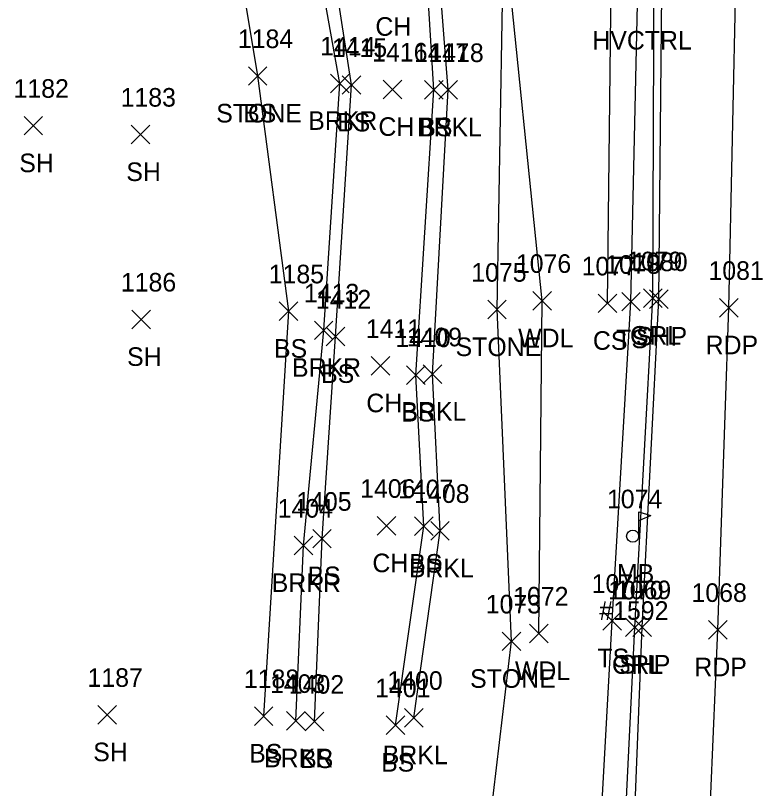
# Model space of a CAD drawing. Extents: x 1618262 to 1622220, y 273782 to 283685.
# Drawn here: x 1621974.4 to 1622054.7, y 282582.4 to 282665.6 of the extents above; entities that cross this region are included whole.
import ezdxf

# ---------------------------------------------------------------- set-up
doc = ezdxf.new("R2010")
doc.units = 0
for name, color, linetype in [('C_A', 7, 'Continuous'), ('L_A', 7, 'Continuous'), ('L_C', 7, 'Continuous'), ('L_I', 7, 'Continuous'), ('L_TIC', 7, 'Continuous'), ('LASF', 7, 'Continuous'), ('LAWA', 7, 'Continuous'), ('LAWE', 7, 'Continuous'), ('LELB', 7, 'Continuous'), ('LMB', 7, 'Continuous'), ('P_A', 7, 'Continuous'), ('P_I', 7, 'Continuous'), ('P_TIC', 7, 'Continuous'), ('PET', 7, 'Continuous'), ('PSP', 7, 'Continuous'), ('R_A', 7, 'Continuous'), ('R_I', 7, 'Continuous'), ('R_TIC', 7, 'Continuous'), ('RGR', 7, 'Continuous')]:
    doc.layers.add(name, color=color, linetype=linetype)

msp = doc.modelspace()

# ---------------------------------------------------------------- linework, layer by layer
at = {"layer": 'L_TIC'}
for points in [[(1621999.409, 282658.069), (1622001.409, 282660.069)], [(1622001.409, 282658.069), (1621999.409, 282660.069)], [(1621999.409, 282658.069), (1622001.409, 282660.069)], [(1622001.409, 282658.069), (1621999.409, 282660.069)], [(1622008.259, 282657.274), (1622010.259, 282659.274)], [(1622010.259, 282657.274), (1622008.259, 282659.274)], [(1622009.519, 282657.102), (1622011.519, 282659.102)], [(1622011.519, 282657.102), (1622009.519, 282659.102)], [(1622013.915, 282656.626), (1622015.915, 282658.626)], [(1622015.915, 282656.626), (1622013.915, 282658.626)], [(1622018.353, 282656.587), (1622020.353, 282658.587)], [(1622020.353, 282656.587), (1622018.353, 282658.587)], [(1622019.908, 282656.569), (1622021.908, 282658.569)], [(1622021.908, 282656.569), (1622019.908, 282658.569)], [(1621975.275, 282652.722), (1621977.275, 282654.722)], [(1621977.275, 282652.722), (1621975.275, 282654.722)], [(1621986.792, 282651.771), (1621988.792, 282653.771)], [(1621988.792, 282651.771), (1621986.792, 282653.771)], [(1622030.019, 282633.894), (1622032.019, 282635.894)], [(1622032.019, 282633.894), (1622030.019, 282635.894)], [(1622037.036, 282633.62), (1622039.036, 282635.62)], [(1622039.036, 282633.62), (1622037.036, 282635.62)], [(1622039.575, 282633.794), (1622041.575, 282635.794)], [(1622041.575, 282633.794), (1622039.575, 282635.794)], [(1622002.727, 282632.768), (1622004.727, 282634.768)], [(1622004.727, 282632.768), (1622002.727, 282634.768)], [(1622025.162, 282632.945), (1622027.162, 282634.945)], [(1622027.162, 282632.945), (1622025.162, 282634.945)], [(1621986.876, 282631.889), (1621988.876, 282633.889)], [(1621988.876, 282631.889), (1621986.876, 282633.889)], [(1622006.513, 282630.716), (1622008.513, 282632.716)], [(1622008.513, 282630.716), (1622006.513, 282632.716)], [(1622007.796, 282630.06), (1622009.796, 282632.06)], [(1622009.796, 282630.06), (1622007.796, 282632.06)], [(1622012.613, 282626.902), (1622014.613, 282628.902)], [(1622014.613, 282626.902), (1622012.613, 282628.902)], [(1622016.432, 282625.905), (1622018.432, 282627.905)], [(1622018.432, 282625.905), (1622016.432, 282627.905)], [(1622018.223, 282625.996), (1622020.223, 282627.996)], [(1622020.223, 282625.996), (1622018.223, 282627.996)], [(1622013.265, 282609.701), (1622015.265, 282611.701)], [(1622015.265, 282609.701), (1622013.265, 282611.701)], [(1622017.278, 282609.651), (1622019.278, 282611.651)], [(1622019.278, 282609.651), (1622017.278, 282611.651)], [(1622019.028, 282609.154), (1622021.028, 282611.154)], [(1622021.028, 282609.154), (1622019.028, 282611.154)], [(1622004.333, 282607.569), (1622006.333, 282609.569)], [(1622006.333, 282607.569), (1622004.333, 282609.569)], [(1622006.334, 282608.31), (1622008.334, 282610.31)], [(1622008.334, 282608.31), (1622006.334, 282610.31)], [(1622037.549, 282599.481), (1622039.549, 282601.481)], [(1622039.549, 282599.481), (1622037.549, 282601.481)], [(1622029.671, 282598.119), (1622031.671, 282600.119)], [(1622031.671, 282598.119), (1622029.671, 282600.119)], [(1622026.724, 282597.268), (1622028.724, 282599.268)], [(1622028.724, 282597.268), (1622026.724, 282599.268)], [(1621983.232, 282589.373), (1621985.232, 282591.373)], [(1621985.232, 282589.373), (1621983.232, 282591.373)], [(1622000.056, 282589.233), (1622002.056, 282591.233)], [(1622002.056, 282589.233), (1622000.056, 282591.233)], [(1622003.508, 282588.719), (1622005.508, 282590.719)], [(1622005.508, 282588.719), (1622003.508, 282590.719)], [(1622005.532, 282588.636), (1622007.532, 282590.636)], [(1622007.532, 282588.636), (1622005.532, 282590.636)], [(1622016.226, 282589.052), (1622018.226, 282591.052)], [(1622018.226, 282589.052), (1622016.226, 282591.052)], [(1622014.253, 282588.258), (1622016.253, 282590.258)], [(1622016.253, 282588.258), (1622014.253, 282590.258)]]:
    msp.add_lwpolyline(points, dxfattribs=at)
at = {"layer": 'LASF'}
msp.add_lwpolyline([(1622017.991, 282482.049), (1622021.545, 282521.435), (1622023.199, 282560.154), (1622027.724, 282598.268), (1622026.162, 282633.945), (1622026.882, 282675.285), (1622029.94, 282679.448), (1622032.966, 282688.79), (1622033.094, 282693.395), (1622031.462, 282708.807), (1622023.774, 282712.352), (1622021.815, 282710.839), (1622017.17, 282709.218), (1622015.049, 282702.038), (1622004.918, 282698.84), (1621996.66, 282681.559), (1622000.409, 282659.069)], dxfattribs=at)
at = {"layer": 'LAWA'}
msp.add_lwpolyline([(1622030.671, 282599.119), (1622031.019, 282634.894), (1622026.882, 282675.285), (1622025.785, 282678.835)], dxfattribs=at)
at = {"layer": 'LAWE'}
for points in [[(1622004.508, 282589.719), (1622005.333, 282608.569), (1622007.513, 282631.716), (1622009.259, 282658.274), (1622005.37, 282679.941), (1622009.389, 282692.601), (1622016.472, 282697.474), (1622023.015, 282700.983)], [(1622017.226, 282590.052), (1622020.028, 282610.154), (1622019.223, 282626.996), (1622020.908, 282657.569), (1622019.553, 282675.131), (1622022.862, 282678.636)]]:
    msp.add_lwpolyline(points, dxfattribs=at)
at = {"layer": 'LELB'}
for points in [[(1622031.53, 282480.209), (1622034.92, 282519.516), (1622036.308, 282559.668), (1622038.549, 282600.481), (1622040.575, 282634.794), (1622041.384, 282671.626), (1622041.057, 282708.261), (1622040.536, 282746.865), (1622039.334, 282766.475), (1622038.366, 282807.145), (1622036.997, 282847.689), (1622035.465, 282881.364), (1622030.123, 282906.905), (1622032.201, 282930.97)], [(1622038.036, 282634.62), (1622038.492, 282672.044), (1622038.146, 282708.503), (1622036.634, 282747.032), (1622027.782, 282767.08)], [(1622015.253, 282589.258), (1622018.278, 282610.651), (1622017.432, 282626.905), (1622019.353, 282657.587), (1622018.302, 282675.18), (1622022.753, 282682.471), (1622023.259, 282685.553), (1622022.974, 282687.958), (1622023.158, 282690.363), (1622022.911, 282694.814), (1622022.926, 282698.21), (1622023.015, 282700.983), (1622022.752, 282703.296)], [(1622006.532, 282589.636), (1622007.334, 282609.31), (1622008.796, 282631.06), (1622010.519, 282658.102), (1622007.168, 282679.656), (1622011.291, 282692.087), (1622017.342, 282696.584), (1622022.926, 282698.21)], [(1622000.409, 282659.069), (1622003.727, 282633.768), (1622001.056, 282590.233)]]:
    msp.add_lwpolyline(points, dxfattribs=at)
at = {"layer": 'LMB'}
for p, q in [((1622041.41, 282612.177), (1622042.704, 282611.795)), ((1622041.416, 282609.585), (1622041.415, 282612.179)), ((1622041.415, 282611.278), (1622042.697, 282611.786)), ((1622040.76, 282609.576), (1622040.76, 282609.576))]:
    msp.add_line(p, q, dxfattribs=at)
msp.add_circle((1622040.76, 282609.576), 0.656, dxfattribs=at)
at = {"layer": 'P_TIC'}
for points in [[(1622042.576, 282634.077), (1622044.576, 282636.077)], [(1622044.576, 282634.077), (1622042.576, 282636.077)], [(1622050.114, 282633.143), (1622052.114, 282635.143)], [(1622052.114, 282633.143), (1622050.114, 282635.143)], [(1622040.775, 282598.797), (1622042.775, 282600.797)], [(1622042.775, 282598.797), (1622040.775, 282600.797)], [(1622048.907, 282598.505), (1622050.907, 282600.505)], [(1622050.907, 282598.505), (1622048.907, 282600.505)]]:
    msp.add_lwpolyline(points, dxfattribs=at)
at = {"layer": 'PET'}
msp.add_lwpolyline([(1622031.404, 282363.078), (1622036.529, 282409.612), (1622039.656, 282443.455), (1622042.912, 282478.81), (1622045.922, 282518.248), (1622048.156, 282558.34), (1622049.907, 282599.505), (1622051.114, 282634.143), (1622051.904, 282670.586), (1622052.331, 282709.809), (1622052.148, 282746.848), (1622051.427, 282768.15), (1622050.471, 282807.305), (1622048.588, 282847.854), (1622046.49, 282883.042), (1622043.219, 282932.276)], dxfattribs=at)
at = {"layer": 'PSP'}
msp.add_lwpolyline([(1622024.53, 282364.695), (1622029.224, 282410.341), (1622032.133, 282444.404), (1622034.721, 282480.169), (1622038.065, 282518.937), (1622040.189, 282559.981), (1622041.775, 282599.797), (1622043.576, 282635.077), (1622043.931, 282671.705), (1622044.179, 282709.624), (1622044.427, 282746.882), (1622044.138, 282766.852), (1622043.312, 282807.356), (1622042.106, 282847.846), (1622040.006, 282882.115), (1622036.278, 282931.352)], dxfattribs=at)
at = {"layer": 'R_TIC'}
for points in [[(1622041.921, 282634.171), (1622043.921, 282636.171)], [(1622043.921, 282634.171), (1622041.921, 282636.171)], [(1622039.978, 282598.772), (1622041.978, 282600.772)], [(1622041.978, 282598.772), (1622039.978, 282600.772)]]:
    msp.add_lwpolyline(points, dxfattribs=at)
at = {"layer": 'RGR'}
msp.add_lwpolyline([(1622023.476, 282364.894), (1622028.185, 282410.184), (1622031.232, 282444.188), (1622033.737, 282480.242), (1622036.802, 282518.899), (1622039.036, 282560.065), (1622040.978, 282599.772), (1622042.921, 282635.171), (1622043.063, 282671.763), (1622043.615, 282709.363), (1622043.681, 282746.97), (1622043.35, 282766.727), (1622042.763, 282807.193), (1622041.251, 282847.718), (1622039.436, 282882.181), (1622035.129, 282907.981)], dxfattribs=at)

# ---------------------------------------------------------------- texts
at = {"layer": 'C_A'}
msp.add_text('HVCTRL', height=2, dxfattribs=at).set_placement((1622036.418, 282661.912))
at = {"layer": 'L_A'}
for s, p in [('CH', (1622013.077, 282663.391)), ('STONE', (1621995.953, 282654.069)), ('BS', (1621998.85, 282654.069)), ('BRKR', (1622005.85, 282653.274)), ('BS', (1622008.96, 282653.102)), ('CH', (1622013.403, 282652.626)), ('BRKL', (1622017.554, 282652.569)), ('BS', (1622017.794, 282652.587)), ('SH', (1621974.763, 282648.722)), ('SH', (1621986.28, 282647.771)), ('WDL', (1622028.436, 282629.894)), ('CS', (1622036.477, 282629.62)), ('TS', (1622038.985, 282629.794)), ('BS', (1622002.168, 282628.768)), ('STONE', (1622021.706, 282628.945)), ('SH', (1621986.364, 282627.889)), ('BRKR', (1622004.103, 282626.716)), ('BS', (1622007.237, 282626.06)), ('CH', (1622012.101, 282622.902)), ('BRKL', (1622015.869, 282621.996)), ('BS', (1622015.873, 282621.905)), ('CH', (1622012.753, 282605.701)), ('BRKL', (1622016.673, 282605.154)), ('BS', (1622016.719, 282605.651)), ('BS', (1622005.775, 282604.31)), ('MB', (1622039.067, 282604.576)), ('BRKR', (1622001.923, 282603.569)), ('TS', (1622036.959, 282595.481)), ('WDL', (1622028.088, 282594.119)), ('STONE', (1622023.267, 282593.268)), ('SH', (1621982.72, 282585.373)), ('BS', (1621999.497, 282585.233)), ('BRKL', (1622013.871, 282585.052)), ('BRKR', (1622001.099, 282584.719)), ('BS', (1622004.973, 282584.636)), ('BS', (1622013.694, 282584.258))]:
    msp.add_text(s, height=2, dxfattribs=at).set_placement(p)
at = {"layer": 'L_C'}
msp.add_text('#1592', height=2, dxfattribs=at).set_placement((1622037.17, 282600.576))
at = {"layer": 'L_I'}
for s, p in [('1184', (1621998.284, 282662.069)), ('1184', (1621998.284, 282662.069)), ('1414', (1622007.134, 282661.274)), ('1415', (1622008.393, 282661.102)), ('1416', (1622012.734, 282660.626)), ('1417', (1622017.227, 282660.587)), ('1418', (1622018.782, 282660.569)), ('1182', (1621974.149, 282656.722)), ('1183', (1621985.666, 282655.771)), ('1076', (1622028.192, 282637.894)), ('1077', (1622035.265, 282637.62)), ('1078', (1622037.804, 282637.794)), ('1185', (1622001.601, 282636.768)), ('1075', (1622023.391, 282636.945)), ('1186', (1621985.696, 282635.889)), ('1413', (1622005.387, 282634.716)), ('1412', (1622006.671, 282634.06)), ('1411', (1622012.054, 282630.902)), ('1410', (1622015.22, 282629.905)), ('1409', (1622016.444, 282629.996)), ('1406', (1622011.439, 282613.701)), ('1407', (1622015.507, 282613.651)), ('1408', (1622017.256, 282613.154)), ('1074', (1622037.988, 282612.576)), ('1405', (1622004.563, 282612.31)), ('1404', (1622002.561, 282611.569)), ('1071', (1622036.345, 282603.481)), ('1072', (1622027.9, 282602.119)), ('1073', (1622024.952, 282601.268)), ('1187', (1621982.107, 282593.373)), ('1188', (1621998.93, 282593.233)), ('1403', (1622001.737, 282592.719)), ('1402', (1622003.761, 282592.636)), ('1400', (1622014.367, 282593.052)), ('1401', (1622013.048, 282592.258))]:
    msp.add_text(s, height=2, dxfattribs=at).set_placement(p)
at = {"layer": 'P_A'}
for s, p in [('SHP', (1622041.112, 282630.077)), ('RDP', (1622048.602, 282629.143)), ('SHP', (1622039.311, 282594.797)), ('RDP', (1622047.395, 282594.505))]:
    msp.add_text(s, height=2, dxfattribs=at).set_placement(p)
at = {"layer": 'P_I'}
for s, p in [('1080', (1622040.718, 282638.077)), ('1081', (1622048.909, 282637.143)), ('1069', (1622038.949, 282602.797)), ('1068', (1622047.088, 282602.505))]:
    msp.add_text(s, height=2, dxfattribs=at).set_placement(p)
at = {"layer": 'R_A'}
for p in [(1622040.464, 282630.171), (1622038.522, 282594.772)]:
    msp.add_text('GRL', height=2, dxfattribs=at).set_placement(p)
at = {"layer": 'R_I'}
for s, p in [('1079', (1622040.141, 282638.171)), ('1070', (1622038.12, 282602.772))]:
    msp.add_text(s, height=2, dxfattribs=at).set_placement(p)

doc.saveas('drawing.dxf')
